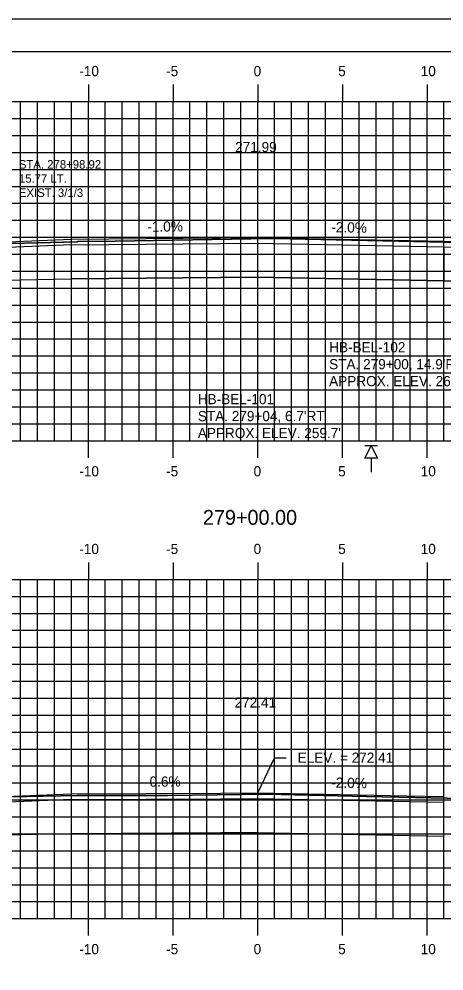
# Model space of a CAD drawing. Extents: x 854676 to 854846, y 366268 to 366378.
# Drawn here: x 854745 to 854770.1, y 366322 to 366378.2 of the extents above; entities that cross this region are included whole.
import ezdxf

# ---------------------------------------------------------------- set-up
doc = ezdxf.new("R2010")
doc.units = 0
for name, color, linetype in [('ANNOTATION', 7, 'Continuous'), ('BORDER', 7, 'Continuous'), ('D_Roadway_Centerline_Text', 7, 'Continuous'), ('D_Roadway_Edge_Shoulder', 7, 'Continuous'), ('D_Roadway_SubGrade', 7, 'Continuous'), ('D_Text_Monospaced', 7, 'Continuous'), ('D_Text_Standard', 7, 'Continuous'), ('H_V ANNOTATION', 7, 'Continuous'), ('JUNK COM EXC', 7, 'Continuous'), ('MAJOR', 7, 'Continuous'), ('MINOR', 7, 'Continuous'), ('PLOT BOUNDARY', 7, 'Continuous'), ('ROCKS', 7, 'Continuous'), ('S_Roadway_Centerline', 7, 'Continuous')]:
    doc.layers.add(name, color=color, linetype=linetype)

msp = doc.modelspace()

# ---------------------------------------------------------------- linework, layer by layer
at = {"layer": 'BORDER'}
msp.add_line((854844.107, 366376.236), (854684.107, 366376.236), dxfattribs=at)
at = {"layer": 'D_Roadway_Edge_Shoulder'}
msp.add_line((854740.106, 366332.158), (854748.106, 366332.478), dxfattribs=at)
for points in [[(854740.106, 366364.866), (854748.106, 366365.186), (854759.106, 366365.296), (854770.106, 366365.076), (854778.106, 366364.755)], [(854748.106, 366332.478), (854756.906, 366332.531), (854759.106, 366332.542), (854767.906, 366332.366), (854770.106, 366332.322)], [(854748.108, 366332.145), (854756.908, 366332.198), (854759.104, 366332.209), (854770.1, 366331.989)]]:
    msp.add_lwpolyline(points, dxfattribs=at)
at = {"layer": 'D_Roadway_SubGrade'}
for points in [[(854748.106, 366364.852), (854740.106, 366364.532), (854740.106, 366362.692), (854748.106, 366362.852)], [(854748.106, 366362.852), (854748.106, 366364.852), (854759.106, 366364.962), (854770.106, 366364.742), (854770.106, 366362.742), (854759.106, 366362.962)], [(854770.106, 366364.742), (854778.107, 366364.422), (854778.107, 366362.582), (854770.106, 366362.742)], [(854748.106, 366332.145), (854740.106, 366331.825), (854740.106, 366329.985), (854748.106, 366330.145)]]:
    msp.add_lwpolyline(points, close=True, dxfattribs=at)
msp.add_lwpolyline([(854748.106, 366330.145), (854756.919, 366330.198), (854759.089, 366330.208), (854770.11, 366329.988)], dxfattribs=at)
at = {"layer": 'D_Text_Standard'}
msp.add_lwpolyline([(854759.106, 366332.542), (854760.106, 366334.618), (854760.786, 366334.618)], dxfattribs=at)
at = {"layer": 'JUNK COM EXC'}
for points in [[(854771.088, 366364.995), (854760.071, 366365.226), (854759.833, 366365.231), (854750.684, 366365.086), (854748.494, 366365.05), (854748.457, 366365.047), (854748.431, 366365.046), (854742.209, 366364.875), (854742.127, 366364.878), (854738.368, 366365.092), (854737.885, 366365.061), (854735.101, 366364.757)], [(854735.101, 366364.757), (854735.101, 366364.291), (854739.106, 366364.21), (854739.106, 366362.672), (854748.106, 366362.852), (854759.106, 366362.962), (854770.106, 366362.742), (854779.106, 366362.562)], [(854771.23, 366332.218), (854765.539, 366332.337), (854759.638, 366332.473), (854753.787, 366332.38), (854748.442, 366332.38), (854744.482, 366332.301), (854742.111, 366332.207), (854741.654, 366332.372), (854738.169, 366332.607), (854737.972, 366332.619), (854737.723, 366332.54), (854735.471, 366332.268), (854733.583, 366332.132), (854731.106, 366332.097), (854731.106, 366330.93), (854739.106, 366330.77), (854739.106, 366329.965), (854748.106, 366330.145), (854759.089, 366330.208), (854770.11, 366329.988)]]:
    msp.add_lwpolyline(points, dxfattribs=at)
at = {"layer": 'MAJOR'}
for p, q in [((854749.106, 366374.311), (854749.106, 366373.309)), ((854754.106, 366374.311), (854754.106, 366373.309)), ((854759.106, 366374.311), (854759.106, 366373.309)), ((854764.106, 366374.311), (854764.106, 366373.309)), ((854769.106, 366374.311), (854769.106, 366373.309)), ((854689.106, 366373.309), (854829.106, 366373.309)), ((854689.106, 366373.309), (854829.106, 366373.309)), ((854749.106, 366353.309), (854749.106, 366373.309)), ((854754.106, 366353.309), (854754.106, 366373.309)), ((854759.106, 366353.309), (854759.106, 366373.309)), ((854764.106, 366353.309), (854764.106, 366373.309)), ((854769.106, 366353.309), (854769.106, 366373.309)), ((854689.106, 366368.309), (854829.106, 366368.309)), ((854689.106, 366363.309), (854829.106, 366363.309)), ((854689.106, 366358.309), (854829.106, 366358.309)), ((854689.106, 366353.309), (854829.106, 366353.309)), ((854689.106, 366353.309), (854829.106, 366353.309)), ((854749.106, 366352.307), (854749.106, 366353.309)), ((854754.106, 366352.307), (854754.106, 366353.309)), ((854759.106, 366352.307), (854759.106, 366353.309)), ((854764.106, 366352.307), (854764.106, 366353.309)), ((854769.106, 366352.307), (854769.106, 366353.309)), ((854749.106, 366346.13), (854749.106, 366345.128)), ((854754.106, 366346.13), (854754.106, 366345.128)), ((854759.106, 366346.13), (854759.106, 366345.128)), ((854764.106, 366346.13), (854764.106, 366345.128)), ((854769.106, 366346.13), (854769.106, 366345.128)), ((854689.106, 366345.128), (854829.106, 366345.128)), ((854689.106, 366345.128), (854829.106, 366345.128)), ((854749.106, 366325.128), (854749.106, 366345.128)), ((854754.106, 366325.128), (854754.106, 366345.128)), ((854759.106, 366325.128), (854759.106, 366345.128)), ((854764.106, 366325.128), (854764.106, 366345.128)), ((854769.106, 366325.128), (854769.106, 366345.128)), ((854689.106, 366340.128), (854829.106, 366340.128)), ((854689.106, 366335.128), (854829.106, 366335.128)), ((854689.106, 366330.128), (854829.106, 366330.128)), ((854689.106, 366325.128), (854829.106, 366325.128)), ((854689.106, 366325.128), (854829.106, 366325.128)), ((854749.106, 366324.126), (854749.106, 366325.128)), ((854754.106, 366324.126), (854754.106, 366325.128)), ((854759.106, 366324.126), (854759.106, 366325.128)), ((854764.106, 366324.126), (854764.106, 366325.128)), ((854769.106, 366324.126), (854769.106, 366325.128))]:
    msp.add_line(p, q, dxfattribs=at)
at = {"layer": 'MINOR'}
for p, q in [((854745.106, 366353.309), (854745.106, 366373.309)), ((854746.106, 366353.309), (854746.106, 366373.309)), ((854747.106, 366353.309), (854747.106, 366373.309)), ((854748.106, 366353.309), (854748.106, 366373.309)), ((854750.106, 366353.309), (854750.106, 366373.309)), ((854751.106, 366353.309), (854751.106, 366373.309)), ((854752.106, 366353.309), (854752.106, 366373.309)), ((854753.106, 366353.309), (854753.106, 366373.309)), ((854755.106, 366353.309), (854755.106, 366373.309)), ((854756.106, 366353.309), (854756.106, 366373.309)), ((854757.106, 366353.309), (854757.106, 366373.309)), ((854758.106, 366353.309), (854758.106, 366373.309)), ((854760.106, 366353.309), (854760.106, 366373.309)), ((854761.106, 366353.309), (854761.106, 366373.309)), ((854762.106, 366353.309), (854762.106, 366373.309)), ((854763.106, 366353.309), (854763.106, 366373.309)), ((854765.106, 366353.309), (854765.106, 366373.309)), ((854766.106, 366353.309), (854766.106, 366373.309)), ((854767.106, 366353.309), (854767.106, 366373.309)), ((854768.106, 366353.309), (854768.106, 366373.309)), ((854770.106, 366353.309), (854770.106, 366373.309)), ((854689.106, 366372.309), (854829.106, 366372.309)), ((854689.106, 366371.309), (854829.106, 366371.309)), ((854689.106, 366370.309), (854829.106, 366370.309)), ((854689.106, 366369.309), (854829.106, 366369.309)), ((854689.106, 366367.309), (854829.106, 366367.309)), ((854689.106, 366366.309), (854829.106, 366366.309)), ((854689.106, 366365.309), (854829.106, 366365.309)), ((854689.106, 366364.309), (854829.106, 366364.309)), ((854689.106, 366362.309), (854829.106, 366362.309)), ((854689.106, 366361.309), (854829.106, 366361.309)), ((854689.106, 366360.309), (854829.106, 366360.309)), ((854689.106, 366359.309), (854829.106, 366359.309)), ((854689.106, 366357.309), (854829.106, 366357.309)), ((854689.106, 366356.309), (854829.106, 366356.309)), ((854689.106, 366355.309), (854829.106, 366355.309)), ((854689.106, 366354.309), (854829.106, 366354.309)), ((854745.106, 366325.128), (854745.106, 366345.128)), ((854746.106, 366325.128), (854746.106, 366345.128)), ((854747.106, 366325.128), (854747.106, 366345.128)), ((854748.106, 366325.128), (854748.106, 366345.128)), ((854750.106, 366325.128), (854750.106, 366345.128)), ((854751.106, 366325.128), (854751.106, 366345.128)), ((854752.106, 366325.128), (854752.106, 366345.128)), ((854753.106, 366325.128), (854753.106, 366345.128)), ((854755.106, 366325.128), (854755.106, 366345.128)), ((854756.106, 366325.128), (854756.106, 366345.128)), ((854757.106, 366325.128), (854757.106, 366345.128)), ((854758.106, 366325.128), (854758.106, 366345.128)), ((854760.106, 366325.128), (854760.106, 366345.128)), ((854761.106, 366325.128), (854761.106, 366345.128)), ((854762.106, 366325.128), (854762.106, 366345.128)), ((854763.106, 366325.128), (854763.106, 366345.128)), ((854765.106, 366325.128), (854765.106, 366345.128)), ((854766.106, 366325.128), (854766.106, 366345.128)), ((854767.106, 366325.128), (854767.106, 366345.128)), ((854768.106, 366325.128), (854768.106, 366345.128)), ((854770.106, 366325.128), (854770.106, 366345.128)), ((854689.106, 366344.128), (854829.106, 366344.128)), ((854689.106, 366343.128), (854829.106, 366343.128)), ((854689.106, 366342.128), (854829.106, 366342.128)), ((854689.106, 366341.128), (854829.106, 366341.128)), ((854689.106, 366339.128), (854829.106, 366339.128)), ((854689.106, 366338.128), (854829.106, 366338.128)), ((854689.106, 366337.128), (854829.106, 366337.128)), ((854689.106, 366336.128), (854829.106, 366336.128)), ((854689.106, 366334.128), (854829.106, 366334.128)), ((854689.106, 366333.128), (854829.106, 366333.128)), ((854689.106, 366332.128), (854829.106, 366332.128)), ((854689.106, 366331.128), (854829.106, 366331.128)), ((854689.106, 366329.128), (854829.106, 366329.128)), ((854689.106, 366328.128), (854829.106, 366328.128)), ((854689.106, 366327.128), (854829.106, 366327.128)), ((854689.106, 366326.128), (854829.106, 366326.128))]:
    msp.add_line(p, q, dxfattribs=at)
at = {"layer": 'PLOT BOUNDARY'}
msp.add_lwpolyline([(854676.013, 366268.177), (854846.013, 366268.177), (854846.013, 366378.177), (854676.013, 366378.177)], close=True, dxfattribs=at)
at = {"layer": 'ROCKS'}
for p, q in [((854766.175, 366353.009), (854765.437, 366353.009)), ((854765.806, 366352.271), (854765.806, 366351.456))]:
    msp.add_line(p, q, dxfattribs=at)
msp.add_lwpolyline([(854765.806, 366353.009), (854766.175, 366352.271), (854765.437, 366352.271)], close=True, dxfattribs=at)
at = {"layer": 'S_Roadway_Centerline'}
for points in [[(854696.367, 366363.291), (854702.494, 366363.706), (854707.878, 366363.872), (854728.577, 366364.293), (854734.737, 366364.717), (854737.885, 366365.061), (854738.368, 366365.092), (854742.127, 366364.878), (854742.209, 366364.875), (854748.431, 366365.046), (854748.457, 366365.047), (854748.494, 366365.05), (854750.684, 366365.086), (854759.833, 366365.231), (854760.071, 366365.226), (854771.088, 366364.995)], [(854708.072, 366331.968), (854708.167, 366331.796), (854708.637, 366331.778), (854708.689, 366331.601), (854709.005, 366331.597), (854711.798, 366331.655), (854722.908, 366331.951), (854728.88, 366332.065), (854733.583, 366332.132), (854735.471, 366332.268), (854737.723, 366332.54), (854737.972, 366332.619), (854738.169, 366332.607), (854741.654, 366332.372), (854742.111, 366332.207), (854744.482, 366332.301), (854748.442, 366332.38), (854753.787, 366332.38), (854759.638, 366332.473), (854765.539, 366332.337), (854771.23, 366332.218)]]:
    msp.add_lwpolyline(points, dxfattribs=at)

# ---------------------------------------------------------------- texts
at = {"layer": 'ANNOTATION'}
for s, rotation, p in [('-1.0%', 0.5729, (854752.591, 366365.63)), ('-2.0%', 358.8542, (854763.449, 366365.609)), ('-0.6%', 0.3323, (854752.456, 366332.903)), ('-2.0%', 358.8542, (854763.449, 366332.855))]:
    msp.add_text(s, height=0.6, rotation=rotation, dxfattribs=at).set_placement(p)
at = {"layer": 'D_Roadway_Centerline_Text'}
for s, p in [('271.99', (854757.774, 366370.328)), ('272.41', (854757.742, 366337.574))]:
    msp.add_text(s, height=0.6, dxfattribs=at).set_placement(p)
at = {"layer": 'D_Text_Monospaced'}
for s, height, p in [('STA. 278+98.92', 0.49998, (854745.007, 366369.358)), ('15.77 LT.', 0.5, (854745.007, 366368.524)), ('EXIST. 3/1/3', 0.49998, (854745.007, 366367.684))]:
    msp.add_text(s, height=height, dxfattribs=at).set_placement(p)
at = {"layer": 'D_Text_Standard'}
msp.add_text('ELEV. = 272.41', height=0.6, dxfattribs=at).set_placement((854761.466, 366334.318))
at = {"layer": 'H_V ANNOTATION'}
for s, height, p in [('-10', 0.6, (854748.571, 366374.809)), ('-5', 0.6, (854753.697, 366374.809)), ('0', 0.6, (854758.865, 366374.809)), ('5', 0.6, (854763.857, 366374.809)), ('10', 0.6, (854768.732, 366374.809)), ('-10', 0.6, (854748.571, 366351.209)), ('-5', 0.6, (854753.697, 366351.209)), ('0', 0.6, (854758.865, 366351.209)), ('5', 0.6, (854763.857, 366351.209)), ('10', 0.6, (854768.732, 366351.209)), ('279+00.00', 0.875, (854755.868, 366348.352)), ('-10', 0.6, (854748.571, 366346.628)), ('-5', 0.6, (854753.697, 366346.628)), ('0', 0.6, (854758.865, 366346.628)), ('5', 0.6, (854763.857, 366346.628)), ('10', 0.6, (854768.732, 366346.628)), ('-10', 0.6, (854748.571, 366323.028)), ('-5', 0.6, (854753.697, 366323.028)), ('0', 0.6, (854758.865, 366323.028)), ('5', 0.6, (854763.857, 366323.028)), ('10', 0.6, (854768.732, 366323.028))]:
    msp.add_text(s, height=height, dxfattribs=at).set_placement(p)
at = {"layer": 'ROCKS'}
for s, p in [('HB-BEL-102', (854763.324, 366358.524)), ("STA. 279+00, 14.9'RT", (854763.324, 366357.524)), ("APPROX. ELEV. 264.6'", (854763.324, 366356.524)), ('HB-BEL-101', (854755.569, 366355.463)), ("STA. 279+04, 6.7'RT", (854755.569, 366354.463)), ("APPROX. ELEV. 259.7'", (854755.569, 366353.463))]:
    msp.add_text(s, height=0.6, dxfattribs=at).set_placement(p)
at = {"layer": 'S_Roadway_Centerline'}
for s, p in [('C', (854759.828, 366365.231)), ('L', (854759.833, 366365.224)), ('C', (854759.633, 366332.473)), ('L', (854759.638, 366332.465))]:
    msp.add_text(s, height=0.0146, dxfattribs=at).set_placement(p)

doc.saveas('drawing.dxf')
